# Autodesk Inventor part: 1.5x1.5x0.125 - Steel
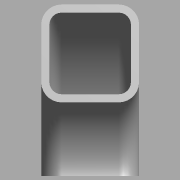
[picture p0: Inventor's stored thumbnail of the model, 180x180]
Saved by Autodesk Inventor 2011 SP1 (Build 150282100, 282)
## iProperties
Created: 2011-03
Part Number: 1.5x1.5x0.125 - Steel
Material: Default
Document SubType Name: Modeling
Designer: bamfomg
Density: 1 g/cm^3
Author: bamfomg
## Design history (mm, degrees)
derived "Square Tube Corners.ipt" dims "d2" = 19.05, "d3" = 19.05, "d6" = 3.175, "d7" = 3.175, "d8" = 3.175, "d12" = 90 deg, "d16" = 1.5875, "d18" = 30 deg, "ID_Rad" = 4.7625, "OD_Rad" = 7.9375, "Side_One" = 38.1, "Side_Two" = 38.1, "Thickness" = 3.175, "Bend_IDRad" = 28.575, "Bevel_Angl" = 30 deg, "Bevel_Dist" = 1.5875
body "Solid1"
feature "Solid1::Square Tube Corners.ipt" dims "d2" = 19.05, "d3" = 19.05, "d6" = 3.175, "d7" = 3.175, "d8" = 3.175, "d12" = 90 deg, "d16" = 1.5875, "d18" = 30 deg, "ID_Rad" = 4.7625, "OD_Rad" = 7.9375, "Side_One" = 38.1, "Side_Two" = 38.1, "Thickness" = 3.175, "Bend_IDRad" = 28.575, "Bevel_Angl" = 30 deg, "Bevel_Dist" = 1.5875, "ScaleForDerivedMember" = 10
tag "TaggingFeature1"
